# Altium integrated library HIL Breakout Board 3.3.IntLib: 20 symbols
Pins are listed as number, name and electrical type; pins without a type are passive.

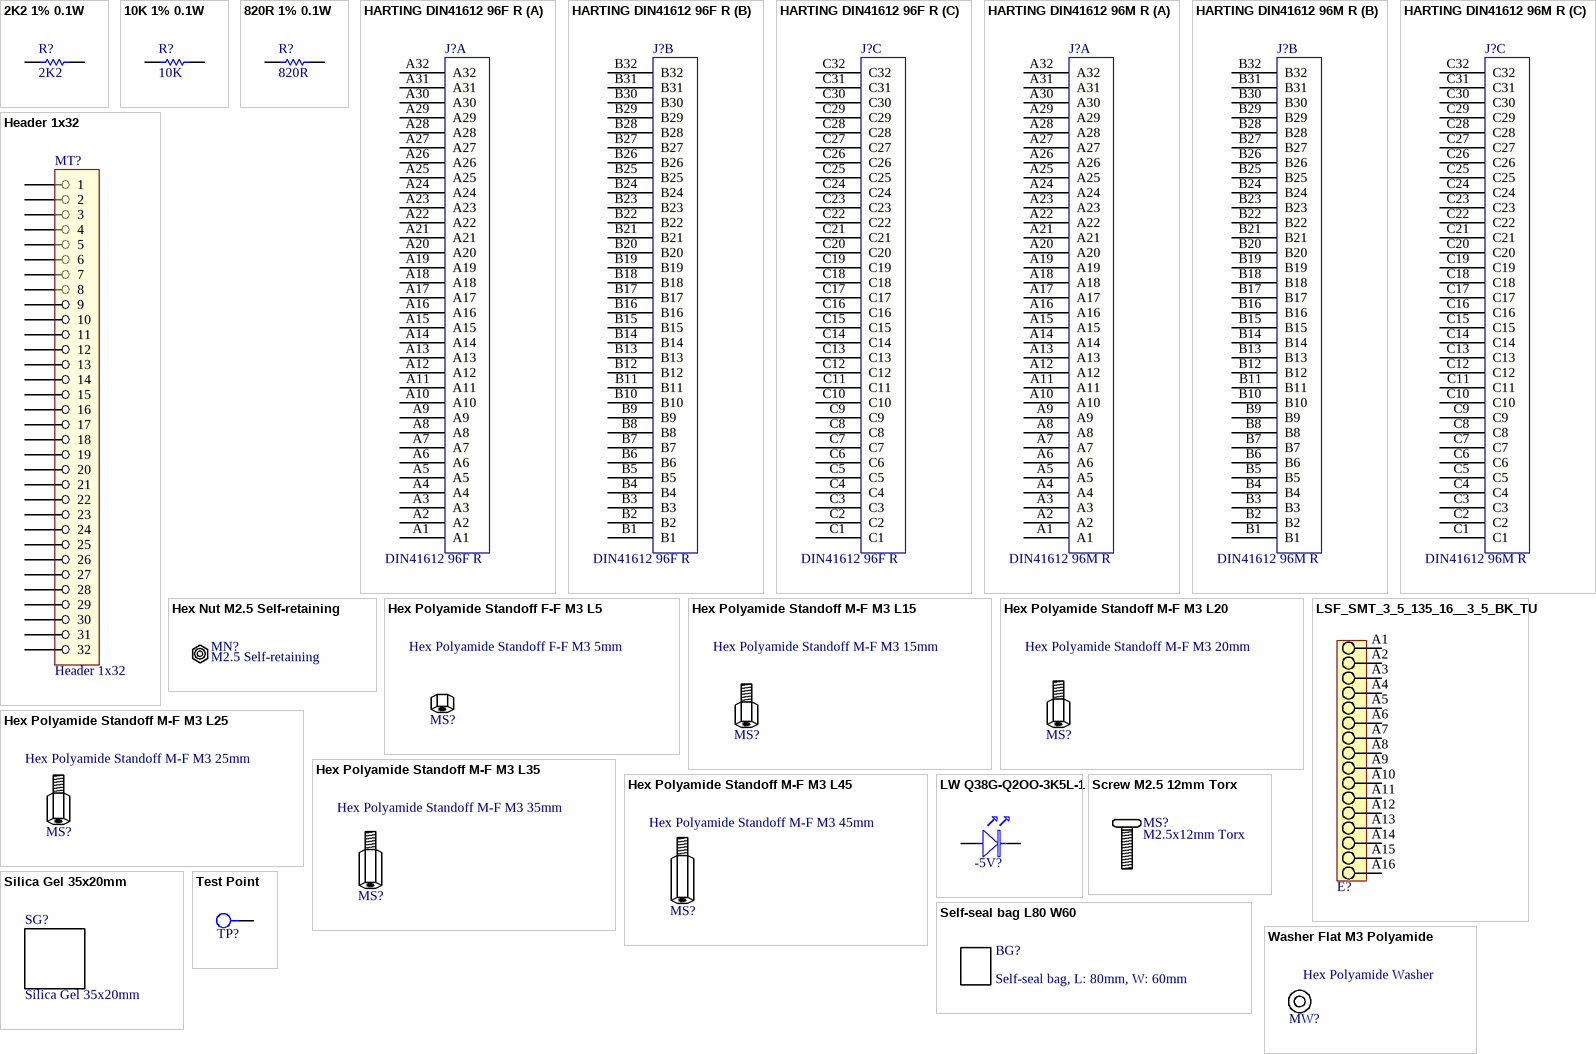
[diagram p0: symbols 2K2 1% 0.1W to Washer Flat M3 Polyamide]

## 2K2 1% 0.1W
designator R?, comment 2K2
2K2 1% 0.1W RESC1608X06; Manufacturer: Panasonic; Manufacturer Code: ERJ-3EKF2201V; Ordering Code: 667-ERJ-3EKF2201V
footprint RESC1608X06L (Chip Resistor, 2-Leads, Body 1.6x0.8mm, IPC High Density)
footprint RESC1608X06M (Chip Resistor, 2-Leads, Body 1.6x0.8mm, IPC Low Density)
footprint RESC1608X06N (Chip Resistor, 2-Leads, Body 1.6x0.8mm, IPC Medium Density)
pins: 1, 2

## 10K 1% 0.1W
designator R?, comment 10K
10K 1% 0.1W RESC1608X06; Manufacturer: Panasonic; Manufacturer Code: ERJ-3EKF1002V; Ordering Code: 667-ERJ-3EKF1002V
footprint RESC1608X06L (Chip Resistor, 2-Leads, Body 1.6x0.8mm, IPC High Density)
footprint RESC1608X06M (Chip Resistor, 2-Leads, Body 1.6x0.8mm, IPC Low Density)
footprint RESC1608X06N (Chip Resistor, 2-Leads, Body 1.6x0.8mm, IPC Medium Density)
pins: 1, 2

## 820R 1% 0.1W
designator R?, comment 820R
820R 1% 0.1W RESC1608X06; Manufacturer: Panasonic; Manufacturer Code: ERJ-3EKF8200V; Ordering Code: 667-ERJ-3EKF8200V
footprint RESC1608X06L (Chip Resistor, 2-Leads, Body 1.6x0.8mm, IPC High Density)
footprint RESC1608X06M (Chip Resistor, 2-Leads, Body 1.6x0.8mm, IPC Low Density)
footprint RESC1608X06N (Chip Resistor, 2-Leads, Body 1.6x0.8mm, IPC Medium Density)
pins: 1, 2

## HARTING DIN41612 96F R
designator J?, comment DIN41612 96F R
Connectors, Female connector, Wave soldering termination, Rated current: ‌2 A, Contacts: 96, Angled, Copper alloy, Noble metal, Mating side, Sn over Ni, Termination side, Performance level: 2, acc. to IEC 60603-2, Coding: Coding with loss of contacts, PCB fixing: With fixing flange, Thermoplastic resin, glass-fibre filled, RAL 7032 (pebble grey); Manufacturer: Harting; Manufacturer Code: 09732966801; Ordering Code: 617-09-73-296-6801
footprint HARTING DIN41612 96F R (R096FS-3,0C1-2, PN: 09732966801)
part A pins: A1, A2, A3, A4, A5, A6, A7, A8, A9, A10, A11, A12, A13, A14, A15, A16, A17, A18, A19, A20, A21, A22, A23, A24, A25, A26, A27, A28, A29, A30, A31, A32
part B pins: B1, B2, B3, B4, B5, B6, B7, B8, B9, B10, B11, B12, B13, B14, B15, B16, B17, B18, B19, B20, B21, B22, B23, B24, B25, B26, B27, B28, B29, B30, B31, B32
part C pins: C1, C2, C3, C4, C5, C6, C7, C8, C9, C10, C11, C12, C13, C14, C15, C16, C17, C18, C19, C20, C21, C22, C23, C24, C25, C26, C27, C28, C29, C30, C31, C32

## HARTING DIN41612 96M R
designator J?, comment DIN41612 96M R
96 pin ABC, RIGHT ANGLE, MALE; Manufacturer: Harting; Manufacturer Code: 09031962921; Ordering Code: 617-09-03-196-2921
footprint HARTING DIN41612 96M R (C096MS-3,0C1-1, PN: 09031962921)
part A pins: A1, A2, A3, A4, A5, A6, A7, A8, A9, A10, A11, A12, A13, A14, A15, A16, A17, A18, A19, A20, A21, A22, A23, A24, A25, A26, A27, A28, A29, A30, A31, A32
part B pins: B1, B2, B3, B4, B5, B6, B7, B8, B9, B10, B11, B12, B13, B14, B15, B16, B17, B18, B19, B20, B21, B22, B23, B24, B25, B26, B27, B28, B29, B30, B31, B32
part C pins: C1, C2, C3, C4, C5, C6, C7, C8, C9, C10, C11, C12, C13, C14, C15, C16, C17, C18, C19, C20, C21, C22, C23, C24, C25, C26, C27, C28, C29, C30, C31, C32

## Header 1x32
designator MT?
BOARD-BOARD CONN, HEADER, 32WAY, 1ROW; Manufacturer: Harwin; Manufacturer Code: M20-9773246; Ordering Code: 855-M20-9773246
footprint HEADER1X32
pins: 1, 2, 3, 4, 5, 6, 7, 8, 9, 10, 11, 12, 13, 14, 15, 16, 17, 18, 19, 20, 21, 22, 23, 24, 25, 26, 27, 28, 29, 30, 31, 32

## Hex Nut M2.5 Self-retaining
designator MN?, comment M2.5 Self-retaining  (mechanical)
Nut; hexagonal; M2.5; A2 stainless steel; Polyamide insert; 100PCS; Manufacturer: KRAFTBERG; Ordering Code: M2.5/D985-A2

## Hex Polyamide Standoff F-F M3 L5
designator MS?, comment Hex Polyamide Standoff F-F M3 5mm  (mechanical)
Screwed spacer sleeve; hexagonal; polyamide; M3; L: 5mm; Manufacturer: DREMEC; Manufacturer Code: 185X05; Ordering Code: TFF-M3X5/DR185

## Hex Polyamide Standoff M-F M3 L15
designator MS?, comment Hex Polyamide Standoff M-F M3 15mm  (mechanical)
Screwed spacer sleeve; hexagonal; polyamide; M3; L: 15mm; Manufacturer: DREMEC; Manufacturer Code: 285X15; Ordering Code: TFM-M3X15/DR285

## Hex Polyamide Standoff M-F M3 L20
designator MS?, comment Hex Polyamide Standoff M-F M3 20mm  (mechanical)
Screwed spacer sleeve; hexagonal; polyamide; M3; L: 20mm; Manufacturer: DREMEC; Manufacturer Code: 285X20; Ordering Code: TFM-M3X20/DR285

## Hex Polyamide Standoff M-F M3 L25
designator MS?, comment Hex Polyamide Standoff M-F M3 25mm  (mechanical)
Screwed spacer sleeve; hexagonal; polyamide; M3; L: 25mm; Manufacturer: DREMEC; Manufacturer Code: 285X25; Ordering Code: TFM-M3X25/DR285

## Hex Polyamide Standoff M-F M3 L35
designator MS?, comment Hex Polyamide Standoff M-F M3 35mm  (mechanical)
Screwed spacer sleeve; hexagonal; polyamide; M3; L: 35mm; Manufacturer: DREMEC; Manufacturer Code: 285X35; Ordering Code: TFM-M3X35/DR285

## Hex Polyamide Standoff M-F M3 L45
designator MS?, comment Hex Polyamide Standoff M-F M3 45mm  (mechanical)
Screwed spacer sleeve; hexagonal; polyamide; M3; L: 45mm; Manufacturer: DREMEC; Manufacturer Code: 285X45; Ordering Code: TFM-M3X45/DR285

## LSF_SMT_3_5_135_16__3_5_BK_TU
designator E?, comment 1885790000  (value not drawn)
OMNIMATE Signal - series LSF; Manufacturer: Weidmüller; Side_termination_characteristic: closed side; Mounting_onto_the_PCB: Reflow solder connection; Pitch_mm: 3,5 mm; Pitch_inch: 0,138 inch; No_of_poles: 16; Contact_material: Cu-Leg; Contact_surface: tinned; Insulating_material: LCP GF; UL_94_flammability_rating: V-0; Rated_voltage_for_surge_voltage_class_pollution_degree_II_2: 320 V; Rated_current_min_no_of_poles_TU_20_deg_C: 17,5 A; Solid_min_H05_07_V_U: 0,2 mm²; Solid_max_H05_07_V_U: 1,5 mm²; Rated_voltage_use_group_B_UL_1059: 300 V; Rated_current_use_group_B_UL_1059: 12 A; Wire_cross_section_AWG_min_UL_1059: AWG 24; Wire_cross_section_AWG_max_UL_1059: AWG 16; Construction_type: PCB Terminal
footprint LSF_SMT_3_5_135_16 (OMNIMATE Signal - Serie LSF  LSF-SMT 3.50/16/135 1.5)
pins: A1, A2, A3, A4, A5, A6, A7, A8, A9, A10, A11, A12, A13, A14, A15, A16
1 alternate drawing of the same symbol

## LW Q38G-Q2OO-3K5L-1
designator -5V?  (value not drawn)
Standard LED - SMD White Diffused 8200K, If=15mA, Vf=2.85V, Case: 0603; Manufacturer: OSRAM Opto Semiconductors; Ordering Code: 720-LWQ38GQ2R23K5L1
footprint 0603L (Chip Diode, DIOC1608X02L,2-Leads, Body 1.60x0.80mm, IPC High Density)
footprint 0603M (Chip Diode, DIOC1608X02M, 2-Leads, Body 1.60x0.80mm, IPC Low Density)
footprint 0603N (Chip Diode, DIOC1608X02N,2-Leads, Body 1.60x0.80mm, IPC Medium Density)
pins: 1 K, 2 A

## Screw M2.5 12mm Torx
designator MS?, comment M2.5x12mm Torx  (mechanical)
Screw; M2,5x12 Head: cheese head; Torx TX08; A2 stainless steel; 100PCS; Manufacturer: BOSSARD; Manufacturer Code: 3108705; Ordering Code: B2.5X12/BN15857

## Self-seal bag L80 W60
designator BG?, comment Self-seal bag, L: 80mm, W: 60mm  (mechanical)
Self-seal bag; L: 80mm; Width: 60mm; Thick: 45um; polyetylene; Ordering Code: PL.TOR60X80

## Silica Gel 35x20mm
designator SG?  (mechanical)
Moisture Absorbing Silica Gel; Size: 35 x 20 mm; Weight: 0.5g, Qty: 500 PCS.; Manufacturer: MULTICOMP PRO; Manufacturer Code: MP004367; Ordering Code: 3495105

## Test Point
designator TP?, comment 1.6mm hole, Qty.: 1PC, 2.4mm MAX PCB thickness  (value not drawn)
MAX PCB thickness: 2.4mm; Mounting hole size: 1.6mm; Qty: 1PCS; Manufacturer: Keystone Electronics; Manufacturer Code: 5006; Ordering Code: 534-5006
footprint TEST POINT 1.6mm HOLE
pins: 1 TP

## Washer Flat M3 Polyamide
designator MW?, comment Hex Polyamide Washer  (mechanical)
WASHER FLAT M3 POLYAMIDE; Manufacturer: Essentra; Ordering Code: 1340111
